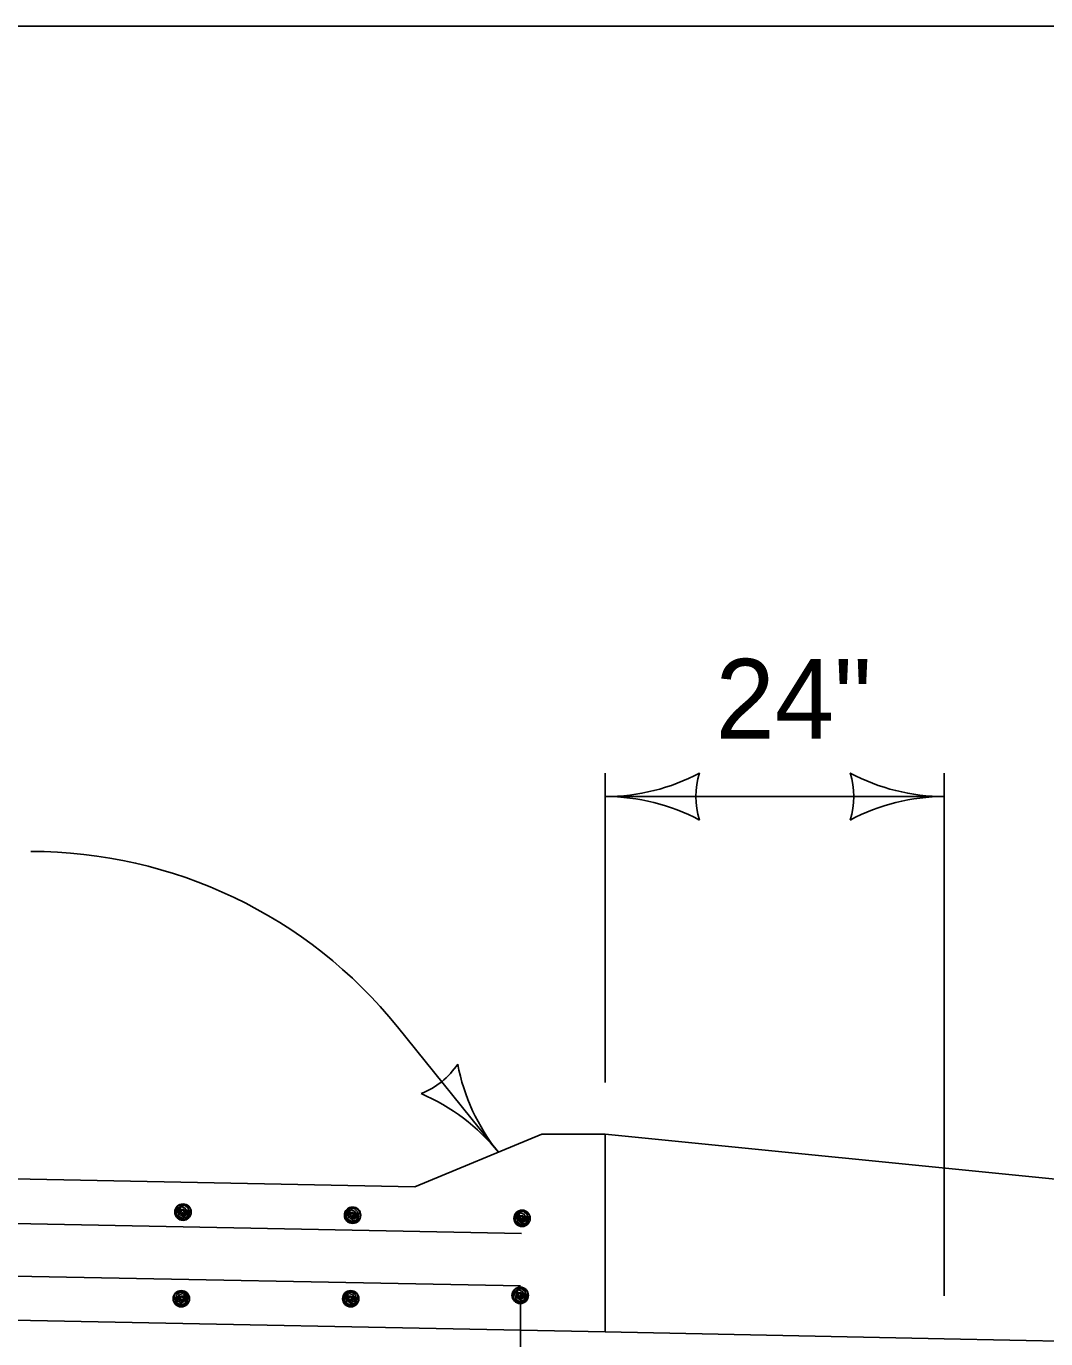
# Model space of a CAD drawing. Extents: x -2134934 to -2124557, y -2139046 to -2134021.
# Drawn here: x -2126851.4 to -2126646.7, y -2137299.6 to -2137035.9 of the extents above; entities that cross this region are included whole.
import ezdxf

# ---------------------------------------------------------------- set-up
doc = ezdxf.new("R2010")
doc.units = 0
for name, color, linetype in [('BridgeSuperStructureExisting', 7, 'Continuous'), ('dsnAlignmentStation', 7, 'Continuous'), ('dsnStdLabel', 7, 'Continuous')]:
    doc.layers.add(name, color=color, linetype=linetype)

msp = doc.modelspace()

# ---------------------------------------------------------------- linework, layer by layer
at = {"layer": 'BridgeSuperStructureExisting'}
for p, q in [((-2126735.17, -2137248.08), (-2126735.17, -2137185.93)), ((-2126667.12, -2137290.93), (-2126667.12, -2137185.93)), ((-2126667.12, -2137190.66), (-2126735.17, -2137190.66)), ((-2126776.91, -2137236.91), (-2126756.64, -2137262.08)), ((-2126773.45, -2137269.05), (-2127483.71, -2137254.79)), ((-2127483.71, -2137254.79), (-2126773.45, -2137269.05)), ((-2126747.94, -2137258.47), (-2126773.45, -2137269.05)), ((-2126773.45, -2137269.05), (-2126747.94, -2137258.47)), ((-2126735.17, -2137258.47), (-2126747.94, -2137258.47)), ((-2126735.17, -2137258.47), (-2126747.94, -2137258.47)), ((-2126735.17, -2137298.18), (-2126735.17, -2137258.47)), ((-2126735.17, -2137298.18), (-2126735.17, -2137258.47)), ((-2126735.17, -2137258.47), (-2126622.9, -2137269.7)), ((-2127483.71, -2137263.74), (-2126752.01, -2137278.43)), ((-2127484.27, -2137283.15), (-2126735.17, -2137298.18)), ((-2127483.14, -2137283.17), (-2126735.17, -2137298.18)), ((-2126752.19, -2137292.66), (-2126752.19, -2137353.4)), ((-2126735.17, -2137298.18), (-2126667.12, -2137299.55)), ((-2126667.12, -2137299.55), (-2126489.26, -2137303.12))]:
    msp.add_line(p, q, dxfattribs=at)
for points in [[(-2126821.48, -2137274.19), (-2126821.21, -2137273.64), (-2126820.91, -2137272.78), (-2126820.02, -2137272.65), (-2126819.25, -2137272.79), (-2126818.56, -2137273.38), (-2126818.66, -2137274.2), (-2126818.82, -2137275.07), (-2126819.53, -2137275.46), (-2126820.26, -2137275.51), (-2126821.2, -2137274.96), (-2126821.25, -2137274.32), (-2126821, -2137273.46), (-2126820.42, -2137272.76), (-2126819.6, -2137272.82), (-2126818.95, -2137273.4), (-2126818.91, -2137274.18), (-2126819.11, -2137275.05), (-2126819.6, -2137275.16), (-2126820.2, -2137275.32), (-2126820.9, -2137274.88), (-2126820.86, -2137274.25), (-2126820.71, -2137273.52), (-2126820.29, -2137273.02), (-2126819.58, -2137273.31), (-2126819.18, -2137273.87), (-2126819.18, -2137274.61), (-2126819.58, -2137274.77), (-2126820.03, -2137274.99), (-2126820.59, -2137274.61), (-2126820.7, -2137274.06), (-2126820.43, -2137273.59), (-2126819.89, -2137273.58), (-2126819.52, -2137273.85), (-2126819.4, -2137274.34), (-2126819.61, -2137274.58), (-2126819.91, -2137274.7), (-2126820.34, -2137274.43), (-2126820.41, -2137274.08), (-2126820.19, -2137273.75), (-2126819.9, -2137273.82), (-2126819.73, -2137274.08), (-2126819.75, -2137274.42), (-2126819.99, -2137274.4), (-2126820.12, -2137274.1)], [(-2126787.45, -2137274.81), (-2126787.17, -2137274.26), (-2126786.87, -2137273.41), (-2126785.98, -2137273.27), (-2126785.22, -2137273.42), (-2126784.52, -2137274), (-2126784.63, -2137274.83), (-2126784.79, -2137275.69), (-2126785.49, -2137276.08), (-2126786.23, -2137276.13), (-2126787.17, -2137275.58), (-2126787.22, -2137274.94), (-2126786.97, -2137274.08), (-2126786.38, -2137273.39), (-2126785.56, -2137273.45), (-2126784.92, -2137274.03), (-2126784.87, -2137274.81), (-2126785.08, -2137275.67), (-2126785.57, -2137275.79), (-2126786.17, -2137275.94), (-2126786.87, -2137275.51), (-2126786.82, -2137274.87), (-2126786.68, -2137274.15), (-2126786.25, -2137273.65), (-2126785.54, -2137273.93), (-2126785.14, -2137274.5), (-2126785.14, -2137275.23), (-2126785.54, -2137275.4), (-2126786, -2137275.61), (-2126786.56, -2137275.23), (-2126786.66, -2137274.69), (-2126786.39, -2137274.22), (-2126785.85, -2137274.21), (-2126785.48, -2137274.48), (-2126785.37, -2137274.97), (-2126785.58, -2137275.2), (-2126785.88, -2137275.33), (-2126786.3, -2137275.06), (-2126786.37, -2137274.71), (-2126786.16, -2137274.38), (-2126785.87, -2137274.45), (-2126785.69, -2137274.71), (-2126785.72, -2137275.05), (-2126785.96, -2137275.03), (-2126786.08, -2137274.73)], [(-2126753.41, -2137275.44), (-2126753.14, -2137274.89), (-2126752.84, -2137274.04), (-2126751.95, -2137273.9), (-2126751.18, -2137274.05), (-2126750.49, -2137274.63), (-2126750.59, -2137275.45), (-2126750.75, -2137276.32), (-2126751.46, -2137276.71), (-2126752.19, -2137276.76), (-2126753.13, -2137276.21), (-2126753.19, -2137275.57), (-2126752.93, -2137274.71), (-2126752.35, -2137274.02), (-2126751.52, -2137274.07), (-2126750.88, -2137274.65), (-2126750.84, -2137275.44), (-2126751.04, -2137276.3), (-2126751.54, -2137276.41), (-2126752.13, -2137276.57), (-2126752.83, -2137276.13), (-2126752.79, -2137275.5), (-2126752.65, -2137274.77), (-2126752.22, -2137274.27), (-2126751.51, -2137274.56), (-2126751.11, -2137275.13), (-2126751.11, -2137275.86), (-2126751.51, -2137276.02), (-2126751.96, -2137276.24), (-2126752.52, -2137275.86), (-2126752.63, -2137275.31), (-2126752.36, -2137274.85), (-2126751.82, -2137274.83), (-2126751.45, -2137275.1), (-2126751.33, -2137275.6), (-2126751.54, -2137275.83), (-2126751.85, -2137275.95), (-2126752.27, -2137275.68), (-2126752.34, -2137275.33), (-2126752.12, -2137275.01), (-2126751.84, -2137275.08), (-2126751.66, -2137275.33), (-2126751.68, -2137275.67), (-2126751.93, -2137275.66), (-2126752.05, -2137275.35)], [(-2126818.8, -2137291.64), (-2126819.05, -2137291.08), (-2126819.31, -2137290.21), (-2126820.19, -2137290.04), (-2126820.97, -2137290.16), (-2126821.68, -2137290.72), (-2126821.61, -2137291.55), (-2126821.49, -2137292.42), (-2126820.8, -2137292.83), (-2126820.06, -2137292.91), (-2126819.1, -2137292.4), (-2126819.03, -2137291.76), (-2126819.25, -2137290.89), (-2126819.8, -2137290.18), (-2126820.63, -2137290.21), (-2126821.29, -2137290.76), (-2126821.37, -2137291.54), (-2126821.2, -2137292.41), (-2126820.71, -2137292.54), (-2126820.12, -2137292.72), (-2126819.4, -2137292.31), (-2126819.42, -2137291.68), (-2126819.54, -2137290.95), (-2126819.94, -2137290.43), (-2126820.66, -2137290.69), (-2126821.08, -2137291.24), (-2126821.11, -2137291.97), (-2126820.72, -2137292.16), (-2126820.28, -2137292.38), (-2126819.7, -2137292.03), (-2126819.57, -2137291.49), (-2126819.83, -2137291), (-2126820.37, -2137290.98), (-2126820.75, -2137291.23), (-2126820.88, -2137291.72), (-2126820.68, -2137291.96), (-2126820.38, -2137292.1), (-2126819.95, -2137291.84), (-2126819.86, -2137291.49), (-2126820.07, -2137291.16), (-2126820.36, -2137291.21), (-2126820.55, -2137291.47), (-2126820.53, -2137291.8), (-2126820.29, -2137291.8), (-2126820.15, -2137291.51)], [(-2126787.81, -2137291.64), (-2126787.56, -2137291.08), (-2126787.29, -2137290.21), (-2126786.41, -2137290.04), (-2126785.63, -2137290.16), (-2126784.92, -2137290.72), (-2126784.99, -2137291.55), (-2126785.12, -2137292.42), (-2126785.81, -2137292.83), (-2126786.54, -2137292.91), (-2126787.5, -2137292.4), (-2126787.58, -2137291.76), (-2126787.36, -2137290.89), (-2126786.8, -2137290.18), (-2126785.98, -2137290.21), (-2126785.31, -2137290.76), (-2126785.24, -2137291.54), (-2126785.41, -2137292.41), (-2126785.9, -2137292.54), (-2126786.48, -2137292.72), (-2126787.2, -2137292.31), (-2126787.19, -2137291.68), (-2126787.07, -2137290.95), (-2126786.66, -2137290.43), (-2126785.94, -2137290.69), (-2126785.52, -2137291.24), (-2126785.49, -2137291.97), (-2126785.89, -2137292.16), (-2126786.33, -2137292.38), (-2126786.9, -2137292.03), (-2126787.04, -2137291.49), (-2126786.77, -2137291), (-2126786.24, -2137290.98), (-2126785.86, -2137291.23), (-2126785.73, -2137291.72), (-2126785.93, -2137291.96), (-2126786.22, -2137292.1), (-2126786.65, -2137291.84), (-2126786.74, -2137291.49), (-2126786.54, -2137291.16), (-2126786.24, -2137291.21), (-2126786.06, -2137291.47), (-2126786.07, -2137291.8), (-2126786.31, -2137291.8), (-2126786.45, -2137291.51)], [(-2126753.77, -2137290.96), (-2126753.53, -2137290.4), (-2126753.26, -2137289.53), (-2126752.38, -2137289.36), (-2126751.6, -2137289.48), (-2126750.89, -2137290.04), (-2126750.96, -2137290.86), (-2126751.08, -2137291.74), (-2126751.77, -2137292.16), (-2126752.51, -2137292.23), (-2126753.47, -2137291.71), (-2126753.54, -2137291.08), (-2126753.33, -2137290.21), (-2126752.77, -2137289.5), (-2126751.94, -2137289.52), (-2126751.28, -2137290.08), (-2126751.2, -2137290.86), (-2126751.37, -2137291.73), (-2126751.86, -2137291.86), (-2126752.45, -2137292.04), (-2126753.17, -2137291.63), (-2126753.15, -2137290.99), (-2126753.03, -2137290.27), (-2126752.63, -2137289.74), (-2126751.91, -2137290.01), (-2126751.49, -2137290.56), (-2126751.46, -2137291.29), (-2126751.85, -2137291.47), (-2126752.29, -2137291.7), (-2126752.87, -2137291.34), (-2126753, -2137290.8), (-2126752.74, -2137290.33), (-2126752.21, -2137290.29), (-2126751.82, -2137290.54), (-2126751.69, -2137291.03), (-2126751.9, -2137291.27), (-2126752.19, -2137291.41), (-2126752.62, -2137291.15), (-2126752.71, -2137290.81), (-2126752.5, -2137290.47), (-2126752.21, -2137290.53), (-2126752.02, -2137290.78), (-2126752.04, -2137291.12), (-2126752.28, -2137291.12), (-2126752.42, -2137290.82)]]:
    msp.add_lwpolyline(points, dxfattribs=at)
for centre in [(-2126819.96, -2137274.12), (-2126785.92, -2137274.74), (-2126751.89, -2137275.37), (-2126820.31, -2137291.51), (-2126786.29, -2137291.51), (-2126752.26, -2137290.83)]:
    msp.add_circle(centre, 1.65, dxfattribs=at)
for centre, radius, start, end in [((-2126735.17, -2137150.48), 40.18, 270, 298.0725), ((-2126735.17, -2137150.48), 40.18, 270, 298.0725), ((-2126701.49, -2137190.65), 15.52, 162.2666, 197.7334), ((-2126701.49, -2137190.65), 15.52, 162.2666, 197.7334), ((-2126700.8, -2137190.65), 15.52, 342.2666, 17.7334), ((-2126667.11, -2137150.48), 40.18, 241.9275, 270), ((-2126700.8, -2137190.65), 15.52, 342.2666, 17.7334), ((-2126667.11, -2137150.48), 40.18, 241.9275, 270), ((-2126735.17, -2137230.83), 40.18, 61.9275, 90), ((-2126735.17, -2137230.83), 40.18, 61.9275, 90), ((-2126667.11, -2137230.83), 40.18, 90, 118.0725), ((-2126667.11, -2137230.83), 40.18, 90, 118.0725), ((-2126850.54, -2137296.19), 94.53, 38.8378, 90), ((-2126777.76, -2137235.84), 15.52, 291.1048, 326.5715), ((-2126725.34, -2137236.89), 40.18, 190.7656, 218.8381), ((-2126787.93, -2137287.28), 40.18, 38.8381, 66.9106)]:
    msp.add_arc(centre, radius, start, end, dxfattribs=at)
at = {"layer": 'dsnAlignmentStation'}
msp.add_lwpolyline([(-2127734.44, -2137035.95), (-2124599.45, -2137035.95), (-2124599.45, -2139045.94), (-2127734.44, -2139045.94)], close=True, dxfattribs=at)
at = {"layer": 'dsnStdLabel'}
msp.add_line((-2126752.19, -2137288.89), (-2127483.74, -2137275.34), dxfattribs=at)

# ---------------------------------------------------------------- texts
msp.add_text('24"', height=16, dxfattribs=at).set_placement((-2126713.05, -2137179.01))

doc.saveas('drawing.dxf')
